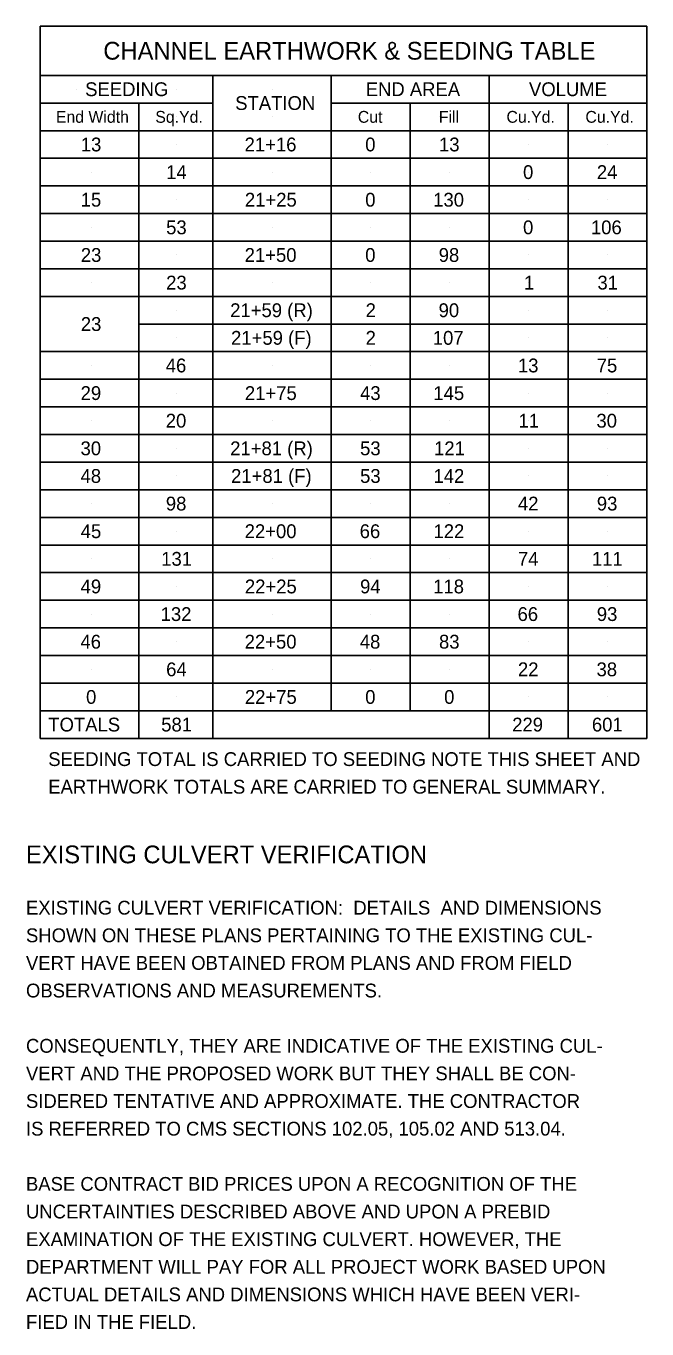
# Model space of a CAD drawing. Extents: x -30 to 76, y -31 to 50.
# Drawn here: x 24.29 to 30.59, y 27.21 to 40.42 of the extents above; entities that cross this region are included whole.
import ezdxf

# ---------------------------------------------------------------- set-up
doc = ezdxf.new("R2010")
doc.units = 0
doc.layers.add('SH_Data', color=7, linetype='Continuous')
doc.layers.add('SH_Text', color=7, linetype='Continuous')

msp = doc.modelspace()

# ---------------------------------------------------------------- linework, layer by layer
at = {"layer": 'SH_Data'}
for p, q in [((24.436, 33.198), (24.436, 40.418)), ((24.436, 40.418), (30.586, 40.418)), ((30.586, 33.198), (30.586, 40.418)), ((30.586, 39.918), (24.436, 39.918)), ((26.186, 33.198), (26.186, 39.918)), ((27.386, 33.478), (27.386, 39.918)), ((28.986, 33.198), (28.986, 39.918)), ((24.805, 39.778), (24.805, 39.778)), ((25.82, 39.778), (25.82, 39.778)), ((26.786, 39.778), (26.786, 39.778)), ((28.186, 39.778), (28.186, 39.778)), ((26.186, 39.638), (24.436, 39.638)), ((25.435, 33.198), (25.435, 39.638)), ((30.586, 39.638), (27.386, 39.638)), ((28.186, 33.478), (28.186, 39.638)), ((29.786, 33.198), (29.786, 39.638)), ((24.955, 39.498), (24.955, 39.498)), ((25.82, 39.498), (25.82, 39.498)), ((26.786, 39.498), (26.786, 39.498)), ((28.487, 39.498), (28.487, 39.498)), ((30.087, 39.498), (30.087, 39.498)), ((30.586, 39.358), (24.436, 39.358)), ((24.955, 39.218), (24.955, 39.218)), ((25.82, 39.218), (25.82, 39.218)), ((26.786, 39.218), (26.786, 39.218)), ((27.786, 39.218), (27.786, 39.218)), ((28.586, 39.218), (28.586, 39.218)), ((29.386, 39.218), (29.386, 39.218)), ((30.186, 39.218), (30.186, 39.218)), ((30.586, 39.078), (24.436, 39.078)), ((24.955, 38.938), (24.955, 38.938)), ((25.82, 38.938), (25.82, 38.938)), ((26.786, 38.938), (26.786, 38.938)), ((27.786, 38.938), (27.786, 38.938)), ((28.586, 38.938), (28.586, 38.938)), ((29.386, 38.938), (29.386, 38.938)), ((30.186, 38.938), (30.186, 38.938)), ((30.586, 38.798), (24.436, 38.798)), ((24.955, 38.658), (24.955, 38.658)), ((25.82, 38.658), (25.82, 38.658)), ((26.786, 38.658), (26.786, 38.658)), ((27.786, 38.658), (27.786, 38.658)), ((28.586, 38.658), (28.586, 38.658)), ((29.386, 38.658), (29.386, 38.658)), ((30.186, 38.658), (30.186, 38.658)), ((30.586, 38.518), (24.436, 38.518)), ((24.955, 38.378), (24.955, 38.378)), ((25.82, 38.378), (25.82, 38.378)), ((26.786, 38.378), (26.786, 38.378)), ((27.786, 38.378), (27.786, 38.378)), ((28.586, 38.378), (28.586, 38.378)), ((29.386, 38.378), (29.386, 38.378)), ((30.186, 38.378), (30.186, 38.378)), ((30.586, 38.238), (24.436, 38.238)), ((24.955, 38.098), (24.955, 38.098)), ((25.82, 38.098), (25.82, 38.098)), ((26.786, 38.098), (26.786, 38.098)), ((27.786, 38.098), (27.786, 38.098)), ((28.586, 38.098), (28.586, 38.098)), ((29.386, 38.098), (29.386, 38.098)), ((30.186, 38.098), (30.186, 38.098)), ((30.586, 37.958), (24.436, 37.958)), ((24.955, 37.818), (24.955, 37.818)), ((25.82, 37.818), (25.82, 37.818)), ((26.786, 37.818), (26.786, 37.818)), ((27.786, 37.818), (27.786, 37.818)), ((28.586, 37.818), (28.586, 37.818)), ((29.386, 37.818), (29.386, 37.818)), ((30.186, 37.818), (30.186, 37.818)), ((30.586, 37.678), (24.436, 37.678)), ((25.82, 37.538), (25.82, 37.538)), ((26.786, 37.538), (26.786, 37.538)), ((27.786, 37.538), (27.786, 37.538)), ((28.586, 37.538), (28.586, 37.538)), ((29.386, 37.538), (29.386, 37.538)), ((30.186, 37.538), (30.186, 37.538)), ((24.955, 37.398), (24.955, 37.398)), ((30.586, 37.398), (25.435, 37.398)), ((25.82, 37.258), (25.82, 37.258)), ((26.786, 37.258), (26.786, 37.258)), ((27.786, 37.258), (27.786, 37.258)), ((28.586, 37.258), (28.586, 37.258)), ((29.386, 37.258), (29.386, 37.258)), ((30.186, 37.258), (30.186, 37.258)), ((30.586, 37.118), (24.436, 37.118)), ((24.955, 36.978), (24.955, 36.978)), ((25.82, 36.978), (25.82, 36.978)), ((26.786, 36.978), (26.786, 36.978)), ((27.786, 36.978), (27.786, 36.978)), ((28.586, 36.978), (28.586, 36.978)), ((29.386, 36.978), (29.386, 36.978)), ((30.186, 36.978), (30.186, 36.978)), ((30.586, 36.838), (24.436, 36.838)), ((24.955, 36.698), (24.955, 36.698)), ((25.82, 36.698), (25.82, 36.698)), ((26.786, 36.698), (26.786, 36.698)), ((27.786, 36.698), (27.786, 36.698)), ((28.586, 36.698), (28.586, 36.698)), ((29.386, 36.698), (29.386, 36.698)), ((30.186, 36.698), (30.186, 36.698)), ((30.586, 36.558), (24.436, 36.558)), ((24.955, 36.418), (24.955, 36.418)), ((25.82, 36.418), (25.82, 36.418)), ((26.786, 36.418), (26.786, 36.418)), ((27.786, 36.418), (27.786, 36.418)), ((28.586, 36.418), (28.586, 36.418)), ((29.386, 36.418), (29.386, 36.418)), ((30.186, 36.418), (30.186, 36.418)), ((30.586, 36.278), (24.436, 36.278)), ((24.955, 36.138), (24.955, 36.138)), ((25.82, 36.138), (25.82, 36.138)), ((26.786, 36.138), (26.786, 36.138)), ((27.786, 36.138), (27.786, 36.138)), ((28.586, 36.138), (28.586, 36.138)), ((29.386, 36.138), (29.386, 36.138)), ((30.186, 36.138), (30.186, 36.138)), ((30.586, 35.998), (24.436, 35.998)), ((24.955, 35.858), (24.955, 35.858)), ((25.82, 35.858), (25.82, 35.858)), ((26.786, 35.858), (26.786, 35.858)), ((27.786, 35.858), (27.786, 35.858)), ((28.586, 35.858), (28.586, 35.858)), ((29.386, 35.858), (29.386, 35.858)), ((30.186, 35.858), (30.186, 35.858)), ((30.586, 35.718), (24.436, 35.718)), ((24.955, 35.578), (24.955, 35.578)), ((25.82, 35.578), (25.82, 35.578)), ((26.786, 35.578), (26.786, 35.578)), ((27.786, 35.578), (27.786, 35.578)), ((28.586, 35.578), (28.586, 35.578)), ((29.386, 35.578), (29.386, 35.578)), ((30.186, 35.578), (30.186, 35.578)), ((30.586, 35.438), (24.436, 35.438)), ((24.955, 35.298), (24.955, 35.298)), ((25.82, 35.298), (25.82, 35.298)), ((26.786, 35.298), (26.786, 35.298)), ((27.786, 35.298), (27.786, 35.298)), ((28.586, 35.298), (28.586, 35.298)), ((29.386, 35.298), (29.386, 35.298)), ((30.186, 35.298), (30.186, 35.298)), ((30.586, 35.158), (24.436, 35.158)), ((24.955, 35.018), (24.955, 35.018)), ((25.82, 35.018), (25.82, 35.018)), ((26.786, 35.018), (26.786, 35.018)), ((27.786, 35.018), (27.786, 35.018)), ((28.586, 35.018), (28.586, 35.018)), ((29.386, 35.018), (29.386, 35.018)), ((30.186, 35.018), (30.186, 35.018)), ((30.586, 34.878), (24.436, 34.878)), ((24.955, 34.738), (24.955, 34.738)), ((25.82, 34.738), (25.82, 34.738)), ((26.786, 34.738), (26.786, 34.738)), ((27.786, 34.738), (27.786, 34.738)), ((28.586, 34.738), (28.586, 34.738)), ((29.386, 34.738), (29.386, 34.738)), ((30.186, 34.738), (30.186, 34.738)), ((30.586, 34.598), (24.436, 34.598)), ((24.955, 34.458), (24.955, 34.458)), ((25.82, 34.458), (25.82, 34.458)), ((26.786, 34.458), (26.786, 34.458)), ((27.786, 34.458), (27.786, 34.458)), ((28.586, 34.458), (28.586, 34.458)), ((29.386, 34.458), (29.386, 34.458)), ((30.186, 34.458), (30.186, 34.458)), ((30.586, 34.318), (24.436, 34.318)), ((24.955, 34.178), (24.955, 34.178)), ((25.82, 34.178), (25.82, 34.178)), ((26.786, 34.178), (26.786, 34.178)), ((27.786, 34.178), (27.786, 34.178)), ((28.586, 34.178), (28.586, 34.178)), ((29.386, 34.178), (29.386, 34.178)), ((30.186, 34.178), (30.186, 34.178)), ((30.586, 34.038), (24.436, 34.038)), ((24.955, 33.898), (24.955, 33.898)), ((25.82, 33.898), (25.82, 33.898)), ((26.786, 33.898), (26.786, 33.898)), ((27.786, 33.898), (27.786, 33.898)), ((28.586, 33.898), (28.586, 33.898)), ((29.386, 33.898), (29.386, 33.898)), ((30.186, 33.898), (30.186, 33.898)), ((30.586, 33.758), (24.436, 33.758)), ((24.955, 33.618), (24.955, 33.618)), ((25.82, 33.618), (25.82, 33.618)), ((26.786, 33.618), (26.786, 33.618)), ((27.786, 33.618), (27.786, 33.618)), ((28.586, 33.618), (28.586, 33.618)), ((29.386, 33.618), (29.386, 33.618)), ((30.186, 33.618), (30.186, 33.618)), ((30.586, 33.478), (24.436, 33.478)), ((25.82, 33.338), (25.82, 33.338)), ((29.386, 33.338), (29.386, 33.338)), ((30.186, 33.338), (30.186, 33.338)), ((30.586, 33.198), (24.436, 33.198))]:
    msp.add_line(p, q, dxfattribs=at)

# ---------------------------------------------------------------- texts
for s, height, p in [('CHANNEL EARTHWORK & SEEDING TABLE', 0.18, (25.075, 40.078)), ('SEEDING', 0.14, (24.891, 39.708)), ('END AREA', 0.14, (27.735, 39.708)), ('VOLUME', 0.14, (29.39, 39.708)), ('STATION', 0.14, (26.412, 39.568)), ('End Width', 0.12, (24.594, 39.438)), ('Sq.Yd.', 0.12, (25.602, 39.438)), ('Cut', 0.12, (27.655, 39.438)), ('Fill', 0.12, (28.476, 39.438)), ('Cu.Yd.', 0.12, (29.162, 39.438)), ('Cu.Yd.', 0.12, (29.962, 39.438)), ('13', 0.14, (24.847, 39.148)), ('21+16', 0.14, (26.507, 39.148)), ('0', 0.14, (27.73, 39.148)), ('13', 0.14, (28.478, 39.148)), ('14', 0.14, (25.712, 38.868)), ('0', 0.14, (29.33, 38.868)), ('24', 0.14, (30.078, 38.868)), ('15', 0.14, (24.846, 38.588)), ('21+25', 0.14, (26.51, 38.588)), ('0', 0.14, (27.73, 38.588)), ('130', 0.14, (28.419, 38.588)), ('53', 0.14, (25.712, 38.308)), ('0', 0.14, (29.33, 38.308)), ('106', 0.14, (30.018, 38.308)), ('23', 0.14, (24.847, 38.028)), ('21+50', 0.14, (26.508, 38.028)), ('0', 0.14, (27.73, 38.028)), ('98', 0.14, (28.475, 38.028)), ('23', 0.14, (25.712, 37.748)), ('1', 0.14, (29.34, 37.748)), ('31', 0.14, (30.084, 37.748)), ('21+59 (R)', 0.14, (26.361, 37.468)), ('2', 0.14, (27.734, 37.468)), ('90', 0.14, (28.474, 37.468)), ('23', 0.14, (24.847, 37.328)), ('21+59 (F)', 0.14, (26.37, 37.188)), ('2', 0.14, (27.734, 37.188)), ('107', 0.14, (28.415, 37.188)), ('46', 0.14, (25.708, 36.908)), ('13', 0.14, (29.278, 36.908)), ('75', 0.14, (30.077, 36.908)), ('29', 0.14, (24.845, 36.628)), ('21+75', 0.14, (26.51, 36.628)), ('43', 0.14, (27.678, 36.628)), ('145', 0.14, (28.421, 36.628)), ('20', 0.14, (25.708, 36.348)), ('11', 0.14, (29.284, 36.348)), ('30', 0.14, (30.074, 36.348)), ('30', 0.14, (24.844, 36.068)), ('21+81 (R)', 0.14, (26.361, 36.068)), ('53', 0.14, (27.678, 36.068)), ('121', 0.14, (28.428, 36.068)), ('48', 0.14, (24.844, 35.788)), ('21+81 (F)', 0.14, (26.37, 35.788)), ('53', 0.14, (27.678, 35.788)), ('142', 0.14, (28.422, 35.788)), ('98', 0.14, (25.709, 35.508)), ('42', 0.14, (29.278, 35.508)), ('93', 0.14, (30.078, 35.508)), ('45', 0.14, (24.846, 35.228)), ('22+00', 0.14, (26.508, 35.228)), ('66', 0.14, (27.674, 35.228)), ('122', 0.14, (28.422, 35.228)), ('131', 0.14, (25.662, 34.948)), ('74', 0.14, (29.278, 34.948)), ('111', 0.14, (30.028, 34.948)), ('49', 0.14, (24.845, 34.668)), ('22+25', 0.14, (26.51, 34.668)), ('94', 0.14, (27.678, 34.668)), ('118', 0.14, (28.419, 34.668)), ('132', 0.14, (25.656, 34.388)), ('66', 0.14, (29.274, 34.388)), ('93', 0.14, (30.078, 34.388)), ('46', 0.14, (24.843, 34.108)), ('22+50', 0.14, (26.508, 34.108)), ('48', 0.14, (27.675, 34.108)), ('83', 0.14, (28.478, 34.108)), ('64', 0.14, (25.712, 33.828)), ('22', 0.14, (29.278, 33.828)), ('38', 0.14, (30.075, 33.828)), ('0', 0.14, (24.9, 33.548)), ('22+75', 0.14, (26.51, 33.548)), ('0', 0.14, (27.73, 33.548)), ('0', 0.14, (28.53, 33.548)), ('TOTALS', 0.14, (24.517, 33.268)), ('581', 0.14, (25.662, 33.268)), ('229', 0.14, (29.22, 33.268)), ('601', 0.14, (30.028, 33.268))]:
    msp.add_text(s, height=height, dxfattribs=at).set_placement(p)
at = {"layer": 'SH_Text'}
for s, height, p in [('SEEDING TOTAL IS CARRIED TO SEEDING NOTE THIS SHEET AND', 0.14, (24.517, 32.918)), ('EARTHWORK TOTALS ARE CARRIED TO GENERAL SUMMARY.', 0.14, (24.517, 32.638)), ('EXISTING CULVERT VERIFICATION', 0.18, (24.291, 31.932)), ('EXISTING CULVERT VERIFICATION:  DETAILS  AND DIMENSIONS', 0.14, (24.291, 31.412)), ('SHOWN ON THESE PLANS PERTAINING TO THE EXISTING CUL-', 0.14, (24.291, 31.132)), ('VERT HAVE BEEN OBTAINED FROM PLANS AND FROM FIELD', 0.14, (24.291, 30.852)), ('OBSERVATIONS AND MEASUREMENTS.', 0.14, (24.291, 30.572)), ('CONSEQUENTLY, THEY ARE INDICATIVE OF THE EXISTING CUL-', 0.14, (24.291, 30.012)), ('VERT AND THE PROPOSED WORK BUT THEY SHALL BE CON-', 0.14, (24.291, 29.732)), ('SIDERED TENTATIVE AND APPROXIMATE. THE CONTRACTOR', 0.14, (24.291, 29.452)), ('IS REFERRED TO CMS SECTIONS 102.05, 105.02 AND 513.04.', 0.14, (24.291, 29.172)), ('BASE CONTRACT BID PRICES UPON A RECOGNITION OF THE', 0.14, (24.291, 28.612)), ('UNCERTAINTIES DESCRIBED ABOVE AND UPON A PREBID', 0.14, (24.291, 28.332)), ('EXAMINATION OF THE EXISTING CULVERT. HOWEVER, THE', 0.14, (24.291, 28.052)), ('DEPARTMENT WILL PAY FOR ALL PROJECT WORK BASED UPON', 0.14, (24.291, 27.772)), ('ACTUAL DETAILS AND DIMENSIONS WHICH HAVE BEEN VERI-', 0.14, (24.291, 27.492)), ('FIED IN THE FIELD.', 0.14, (24.291, 27.212))]:
    msp.add_text(s, height=height, dxfattribs=at).set_placement(p)

doc.saveas('drawing.dxf')
